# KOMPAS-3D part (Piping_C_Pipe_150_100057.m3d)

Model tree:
1. Plane XY
2. Plane ZX
3. Plane ZY
4. X Axis
5. Y Axis
6. Z Axis
7. Origin
8. Path  (labels: Задвижка Dy 150; Труба Dy 150)
9. Plane of section
10. Section of pipe
11. Pipe
     Толщина стенки 1 = 1

Referenced files in C:\Program Files\ASCON\KOMPAS-3D V10\Libs\Piping\Models\Tanks\: Tanks.a3d
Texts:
  Pipe Dn 150
  Steel ASTM A295
  Three Point Plane
  Plane at Angle
  Line and Point Plane
  Axis through Two Vertices
  Axis of Feature
  Axis of Conical Surface
  Axis through Edge
  Приклеить элемент выдавливания
  Приклеить элемент вращения
  Приклеить кинематический элемент
  Приклеить элемент по сечениям
  Trim by Surface
  Trim by Sketch
  Feature with No History
  Intersection Axis of Two Planes
  Two Line Plane
  Line and Face Plane
  Bend by line
  Hole in sheet body
  Cut in sheet body
  Point in CM
  Linear Dimension from Line to Point
  Surface Finish Symbol
  Geometric Tolerance Symbol
  Текст на чертеже
  Линия-выноска #1
  Линия-выноска #2
  Линия-выноска #3
  Отклонения формы и база
  Марка координационной оси
  Марка/позиционное обозначение с линией-выноской
  Марка/позиционное обозначение на линии
  Марка/позиционное обозначение без линии-выноски
  Задвижка Dy 150
  Труба Dy 150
